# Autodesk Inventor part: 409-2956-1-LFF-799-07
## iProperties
Created: 2010-11
Part Number: 409-2956-1-LFF-799-07
Material: 3/4" OD TUBE - SS
Document SubType Name: Modeling
Designer: S. Boerckel
Engineer: Steve Boerckel
Density: 8.08 g/cm^3
Description: DRAIN TUBING
Mass: 332.362 g
Surface Area: 500.097 cm^2
Volume: 41.134 cm^3
Length: 17.945 in
Author: S. Boerckel
Revision Number: 0
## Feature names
1. TaggingFeature1
